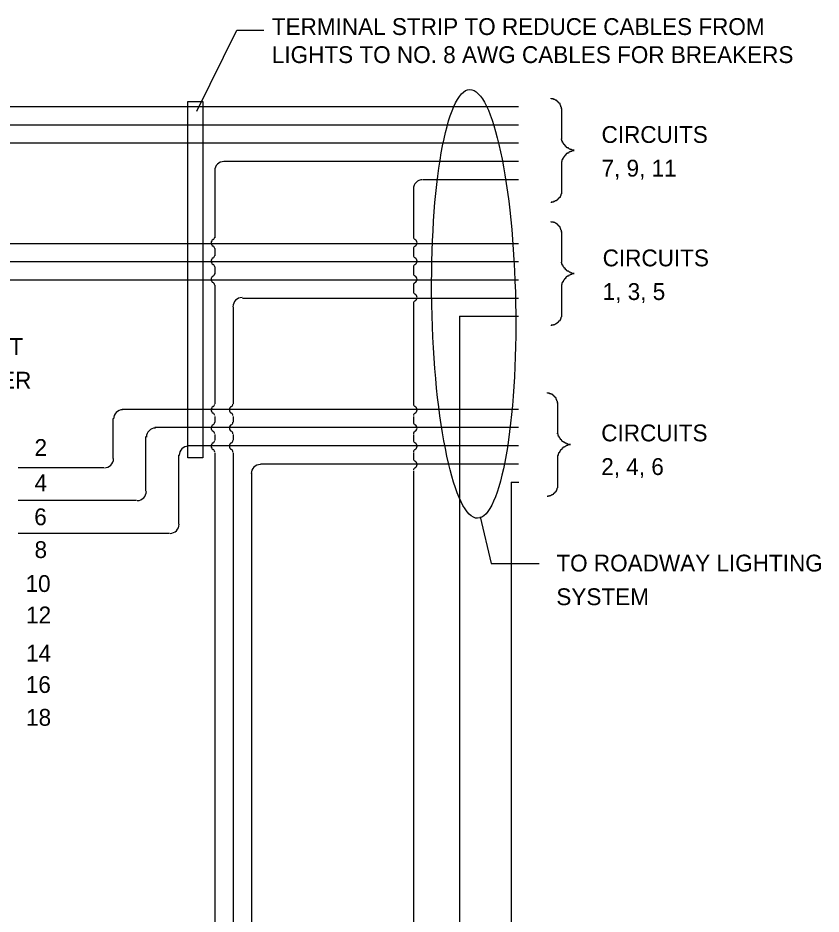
# Model space of a CAD drawing. Extents: x 10006.6 to 10036.5, y 10000 to 10010.3.
# Drawn here: x 10033.106 to 10035.968, y 10007.122 to 10010.317 of the extents above; entities that cross this region are included whole.
import ezdxf

# ---------------------------------------------------------------- set-up
doc = ezdxf.new("R2010")
doc.units = 0
for name, color, linetype in [('Default', 7, 'Continuous'), ('DETL-LINE', 7, 'Continuous'), ('DETL-NOTE', 7, 'Continuous'), ('TTLB-TEXT', 7, 'Continuous')]:
    doc.layers.add(name, color=color, linetype=linetype)

msp = doc.modelspace()

# ---------------------------------------------------------------- linework, layer by layer
at = {"layer": 'Default'}
msp.add_lwpolyline([(10033.7652, 10008.7486), (10033.7118, 10008.7486), (10033.7118, 10010.0192), (10033.7652, 10010.0192)], close=True, dxfattribs=at)
at = {"layer": 'DETL-LINE'}
for p, q in [((10031.28, 10010.001), (10034.89, 10010.001)), ((10031.378, 10009.936), (10034.89, 10009.936)), ((10031.475, 10009.871), (10034.89, 10009.871)), ((10033.841, 10009.806), (10034.89, 10009.806)), ((10033.809, 10009.533), (10033.809, 10009.773)), ((10034.55, 10009.741), (10034.89, 10009.741)), ((10034.517, 10009.533), (10034.517, 10009.708)), ((10031.677, 10009.513), (10034.89, 10009.513)), ((10033.809, 10009.468), (10033.809, 10009.494)), ((10034.517, 10009.468), (10034.517, 10009.494)), ((10031.774, 10009.448), (10034.89, 10009.448)), ((10033.809, 10009.403), (10033.809, 10009.429)), ((10034.517, 10009.403), (10034.517, 10009.429)), ((10031.891, 10009.383), (10034.89, 10009.383)), ((10033.809, 10008.941), (10033.809, 10009.364)), ((10034.517, 10009.338), (10034.517, 10009.364)), ((10033.906, 10009.318), (10034.89, 10009.318)), ((10033.874, 10008.941), (10033.874, 10009.286)), ((10034.517, 10008.941), (10034.517, 10009.299)), ((10034.6795, 10009.253), (10034.89, 10009.253)), ((10033.477, 10008.922), (10034.89, 10008.922)), ((10033.809, 10008.876), (10033.809, 10008.896)), ((10033.874, 10008.876), (10033.874, 10008.896)), ((10034.517, 10008.876), (10034.517, 10008.896)), ((10033.445, 10008.746), (10033.445, 10008.889)), ((10033.594, 10008.857), (10034.89, 10008.857)), ((10033.562, 10008.629), (10033.562, 10008.824)), ((10033.809, 10008.811), (10033.809, 10008.831)), ((10033.874, 10008.811), (10033.874, 10008.831)), ((10034.517, 10008.811), (10034.517, 10008.831)), ((10033.711, 10008.792), (10034.89, 10008.792)), ((10033.679, 10008.512), (10033.679, 10008.759)), ((10033.809, 10006.452), (10033.809, 10008.766)), ((10033.874, 10006.341), (10033.874, 10008.766)), ((10034.517, 10008.746), (10034.517, 10008.766)), ((10033.107, 10008.714), (10033.412, 10008.714)), ((10033.971, 10008.727), (10034.89, 10008.727)), ((10033.939, 10006.237), (10033.939, 10008.694)), ((10034.517, 10005.9973), (10034.517, 10008.701)), ((10034.864, 10008.662), (10034.8915, 10008.662)), ((10033.107, 10008.597), (10033.529, 10008.597)), ((10033.107, 10008.48), (10033.646, 10008.48))]:
    msp.add_line(p, q, dxfattribs=at)
for centre, radius, start, end in [((10033.8399, 10009.7723), 0.0325, 90, 180), ((10034.548, 10009.7073), 0.0325, 90, 180), ((10033.7976, 10009.5351), 0.00975, 295.3769, 0), ((10034.5253, 10009.5351), 0.00975, 180, 244.6231), ((10033.8074, 10009.5146), 0.013, 115.3769, 244.6231), ((10034.5155, 10009.5146), 0.013, 295.3769, 64.6231), ((10033.7976, 10009.494), 0.00975, 0, 64.6231), ((10034.5253, 10009.494), 0.00975, 115.3769, 180), ((10033.8074, 10009.4496), 0.013, 115.3769, 244.6231), ((10033.7976, 10009.4701), 0.00975, 295.3769, 0), ((10034.5253, 10009.4701), 0.00975, 180, 244.6231), ((10034.5155, 10009.4496), 0.013, 295.3769, 64.6231), ((10033.7976, 10009.429), 0.00975, 0, 64.6231), ((10034.5253, 10009.429), 0.00975, 115.3769, 180), ((10033.8074, 10009.3846), 0.013, 115.3769, 244.6231), ((10033.7976, 10009.4051), 0.00975, 295.3769, 0), ((10034.5253, 10009.4051), 0.00975, 180, 244.6231), ((10034.5155, 10009.3846), 0.013, 295.3769, 64.6231), ((10033.7976, 10009.364), 0.00975, 0, 64.6231), ((10034.5253, 10009.364), 0.00975, 115.3769, 180), ((10033.9049, 10009.2871), 0.0325, 90, 180), ((10034.5253, 10009.3401), 0.00975, 180, 244.6231), ((10034.5155, 10009.3196), 0.013, 295.3769, 64.6231), ((10034.5253, 10009.299), 0.00975, 115.3769, 180), ((10033.8074, 10008.9195), 0.013, 115.3769, 244.6231), ((10033.7976, 10008.9401), 0.00975, 295.3769, 0), ((10033.8724, 10008.9195), 0.013, 115.3769, 244.6231), ((10033.8626, 10008.9401), 0.00975, 295.3769, 0), ((10034.5253, 10008.9401), 0.00975, 180, 244.6231), ((10034.5155, 10008.9195), 0.013, 295.3769, 64.6231), ((10033.4791, 10008.887), 0.0325, 90, 180), ((10033.7976, 10008.899), 0.00975, 0, 64.6231), ((10033.8626, 10008.899), 0.00975, 0, 64.6231), ((10034.5253, 10008.899), 0.00975, 115.3769, 180), ((10033.8074, 10008.8545), 0.013, 115.3769, 244.6231), ((10033.7976, 10008.8751), 0.00975, 295.3769, 0), ((10033.8724, 10008.8545), 0.013, 115.3769, 244.6231), ((10033.8626, 10008.8751), 0.00975, 295.3769, 0), ((10034.5253, 10008.8751), 0.00975, 180, 244.6231), ((10034.5155, 10008.8545), 0.013, 295.3769, 64.6231), ((10033.5961, 10008.822), 0.0325, 90, 180), ((10033.7976, 10008.834), 0.00975, 0, 64.6231), ((10033.8626, 10008.834), 0.00975, 0, 64.6231), ((10034.5253, 10008.834), 0.00975, 115.3769, 180), ((10033.8074, 10008.7895), 0.013, 115.3769, 244.6231), ((10033.7976, 10008.8101), 0.00975, 295.3769, 0), ((10033.8724, 10008.7895), 0.013, 115.3769, 244.6231), ((10033.8626, 10008.8101), 0.00975, 295.3769, 0), ((10034.5253, 10008.8101), 0.00975, 180, 244.6231), ((10034.5155, 10008.7895), 0.013, 295.3769, 64.6231), ((10033.7131, 10008.757), 0.0325, 90, 180), ((10033.7976, 10008.769), 0.00975, 0, 64.6231), ((10033.8626, 10008.769), 0.00975, 0, 64.6231), ((10034.5253, 10008.769), 0.00975, 115.3769, 180), ((10033.4141, 10008.7455), 0.0325, 270, 0), ((10034.5253, 10008.7451), 0.00975, 180, 244.6231), ((10034.5155, 10008.7245), 0.013, 295.3769, 64.6231), ((10033.9699, 10008.692), 0.0325, 90, 180), ((10034.5253, 10008.704), 0.00975, 115.3769, 180), ((10033.5311, 10008.6285), 0.0325, 270, 0), ((10033.6481, 10008.5115), 0.0325, 270, 0)]:
    msp.add_arc(centre, radius, start, end, dxfattribs=at)
at = {"layer": 'DETL-NOTE'}
for p, q in [((10034.794, 10008.371), (10034.755, 10008.538)), ((10034.793, 10008.371), (10034.964, 10008.371))]:
    msp.add_line(p, q, dxfattribs=at)
for points in [[(10033.7438, 10009.9846), (10033.8862, 10010.2729), (10033.9824, 10010.2729)], [(10035.043, 10009.992), (10035.043, 10009.994), (10035.043, 10009.996), (10035.043, 10009.998), (10035.041, 10010), (10035.041, 10010.002), (10035.041, 10010.004), (10035.04, 10010.004), (10035.04, 10010.006), (10035.04, 10010.007), (10035.038, 10010.007), (10035.038, 10010.009), (10035.038, 10010.011), (10035.036, 10010.011), (10035.036, 10010.013), (10035.034, 10010.013), (10035.034, 10010.015), (10035.032, 10010.015), (10035.032, 10010.017), (10035.03, 10010.017), (10035.03, 10010.019), (10035.028, 10010.019), (10035.028, 10010.021), (10035.026, 10010.021), (10035.026, 10010.023), (10035.024, 10010.023), (10035.023, 10010.023), (10035.023, 10010.024), (10035.021, 10010.024), (10035.019, 10010.026), (10035.017, 10010.026), (10035.015, 10010.026), (10035.015, 10010.028), (10035.013, 10010.028), (10035.011, 10010.028), (10035.009, 10010.028), (10035.007, 10010.028), (10035.007, 10010.03)], [(10035.043, 10009.994), (10035.043, 10009.885)], [(10035.089, 10009.845), (10035.087, 10009.845), (10035.085, 10009.845), (10035.083, 10009.845), (10035.081, 10009.845), (10035.079, 10009.847), (10035.077, 10009.847), (10035.075, 10009.847), (10035.074, 10009.849), (10035.072, 10009.849), (10035.07, 10009.851), (10035.068, 10009.851), (10035.068, 10009.853), (10035.066, 10009.853), (10035.064, 10009.853), (10035.064, 10009.854), (10035.062, 10009.854), (10035.062, 10009.856), (10035.06, 10009.856), (10035.06, 10009.858), (10035.058, 10009.858), (10035.058, 10009.86), (10035.057, 10009.86), (10035.057, 10009.862), (10035.055, 10009.862), (10035.055, 10009.864), (10035.053, 10009.864), (10035.053, 10009.866), (10035.051, 10009.868), (10035.051, 10009.87), (10035.049, 10009.87), (10035.049, 10009.871), (10035.049, 10009.873), (10035.047, 10009.873), (10035.047, 10009.875), (10035.047, 10009.877), (10035.045, 10009.877), (10035.045, 10009.879), (10035.045, 10009.881), (10035.045, 10009.883), (10035.043, 10009.883), (10035.043, 10009.885)], [(10035.089, 10009.843), (10035.087, 10009.843), (10035.085, 10009.843), (10035.083, 10009.843), (10035.081, 10009.843), (10035.079, 10009.841), (10035.077, 10009.841), (10035.075, 10009.841), (10035.074, 10009.839), (10035.072, 10009.839), (10035.07, 10009.837), (10035.068, 10009.837), (10035.068, 10009.835), (10035.066, 10009.835), (10035.064, 10009.835), (10035.064, 10009.834), (10035.062, 10009.834), (10035.062, 10009.832), (10035.06, 10009.832), (10035.06, 10009.83), (10035.058, 10009.83), (10035.058, 10009.828), (10035.057, 10009.828), (10035.057, 10009.826), (10035.055, 10009.826), (10035.055, 10009.824), (10035.053, 10009.824), (10035.053, 10009.822), (10035.051, 10009.82), (10035.051, 10009.818), (10035.049, 10009.818), (10035.049, 10009.817), (10035.049, 10009.815), (10035.047, 10009.815), (10035.047, 10009.813), (10035.047, 10009.811), (10035.045, 10009.811), (10035.045, 10009.809), (10035.045, 10009.807), (10035.045, 10009.805), (10035.043, 10009.805), (10035.043, 10009.803)], [(10035.043, 10009.803), (10035.043, 10009.694)], [(10035.043, 10009.696), (10035.043, 10009.694), (10035.043, 10009.692), (10035.043, 10009.69), (10035.041, 10009.688), (10035.041, 10009.686), (10035.041, 10009.684), (10035.04, 10009.684), (10035.04, 10009.682), (10035.04, 10009.681), (10035.038, 10009.681), (10035.038, 10009.679), (10035.038, 10009.677), (10035.036, 10009.677), (10035.036, 10009.675), (10035.034, 10009.675), (10035.034, 10009.673), (10035.032, 10009.673), (10035.032, 10009.671), (10035.03, 10009.671), (10035.03, 10009.669), (10035.028, 10009.669), (10035.028, 10009.667), (10035.026, 10009.667), (10035.026, 10009.665), (10035.024, 10009.665), (10035.023, 10009.665), (10035.023, 10009.664), (10035.021, 10009.664), (10035.019, 10009.662), (10035.017, 10009.662), (10035.015, 10009.662), (10035.015, 10009.66), (10035.013, 10009.66), (10035.011, 10009.66), (10035.009, 10009.66), (10035.007, 10009.66), (10035.007, 10009.658)], [(10035.043, 10009.553), (10035.043, 10009.555), (10035.043, 10009.557), (10035.043, 10009.559), (10035.041, 10009.561), (10035.041, 10009.563), (10035.041, 10009.565), (10035.04, 10009.565), (10035.04, 10009.567), (10035.04, 10009.568), (10035.038, 10009.568), (10035.038, 10009.57), (10035.038, 10009.572), (10035.036, 10009.572), (10035.036, 10009.574), (10035.034, 10009.574), (10035.034, 10009.576), (10035.032, 10009.576), (10035.032, 10009.578), (10035.03, 10009.578), (10035.03, 10009.58), (10035.028, 10009.58), (10035.028, 10009.582), (10035.026, 10009.582), (10035.026, 10009.584), (10035.024, 10009.584), (10035.023, 10009.584), (10035.023, 10009.585), (10035.021, 10009.585), (10035.019, 10009.587), (10035.017, 10009.587), (10035.015, 10009.587), (10035.015, 10009.589), (10035.013, 10009.589), (10035.011, 10009.589), (10035.009, 10009.589), (10035.007, 10009.589), (10035.007, 10009.591)], [(10035.043, 10009.555), (10035.043, 10009.446)], [(10035.089, 10009.406), (10035.087, 10009.406), (10035.085, 10009.406), (10035.083, 10009.406), (10035.081, 10009.406), (10035.079, 10009.408), (10035.077, 10009.408), (10035.075, 10009.408), (10035.074, 10009.41), (10035.072, 10009.41), (10035.07, 10009.412), (10035.068, 10009.412), (10035.068, 10009.414), (10035.066, 10009.414), (10035.064, 10009.414), (10035.064, 10009.415), (10035.062, 10009.415), (10035.062, 10009.417), (10035.06, 10009.417), (10035.06, 10009.419), (10035.058, 10009.419), (10035.058, 10009.421), (10035.057, 10009.421), (10035.057, 10009.423), (10035.055, 10009.423), (10035.055, 10009.425), (10035.053, 10009.425), (10035.053, 10009.427), (10035.051, 10009.429), (10035.051, 10009.431), (10035.049, 10009.431), (10035.049, 10009.432), (10035.049, 10009.434), (10035.047, 10009.434), (10035.047, 10009.436), (10035.047, 10009.438), (10035.045, 10009.438), (10035.045, 10009.44), (10035.045, 10009.442), (10035.045, 10009.444), (10035.043, 10009.444), (10035.043, 10009.446)], [(10035.089, 10009.404), (10035.087, 10009.404), (10035.085, 10009.404), (10035.083, 10009.404), (10035.081, 10009.404), (10035.079, 10009.402), (10035.077, 10009.402), (10035.075, 10009.402), (10035.074, 10009.4), (10035.072, 10009.4), (10035.07, 10009.398), (10035.068, 10009.398), (10035.068, 10009.396), (10035.066, 10009.396), (10035.064, 10009.396), (10035.064, 10009.395), (10035.062, 10009.395), (10035.062, 10009.393), (10035.06, 10009.393), (10035.06, 10009.391), (10035.058, 10009.391), (10035.058, 10009.389), (10035.057, 10009.389), (10035.057, 10009.387), (10035.055, 10009.387), (10035.055, 10009.385), (10035.053, 10009.385), (10035.053, 10009.383), (10035.051, 10009.381), (10035.051, 10009.379), (10035.049, 10009.379), (10035.049, 10009.378), (10035.049, 10009.376), (10035.047, 10009.376), (10035.047, 10009.374), (10035.047, 10009.372), (10035.045, 10009.372), (10035.045, 10009.37), (10035.045, 10009.368), (10035.045, 10009.366), (10035.043, 10009.366), (10035.043, 10009.364)], [(10035.043, 10009.364), (10035.043, 10009.255)], [(10035.043, 10009.257), (10035.043, 10009.255), (10035.043, 10009.253), (10035.043, 10009.251), (10035.041, 10009.249), (10035.041, 10009.247), (10035.041, 10009.245), (10035.04, 10009.245), (10035.04, 10009.243), (10035.04, 10009.242), (10035.038, 10009.242), (10035.038, 10009.24), (10035.038, 10009.238), (10035.036, 10009.238), (10035.036, 10009.236), (10035.034, 10009.236), (10035.034, 10009.234), (10035.032, 10009.234), (10035.032, 10009.232), (10035.03, 10009.232), (10035.03, 10009.23), (10035.028, 10009.23), (10035.028, 10009.228), (10035.026, 10009.228), (10035.026, 10009.226), (10035.024, 10009.226), (10035.023, 10009.226), (10035.023, 10009.225), (10035.021, 10009.225), (10035.019, 10009.223), (10035.017, 10009.223), (10035.015, 10009.223), (10035.015, 10009.221), (10035.013, 10009.221), (10035.011, 10009.221), (10035.009, 10009.221), (10035.007, 10009.221), (10035.007, 10009.219)], [(10035.029, 10008.943), (10035.029, 10008.945), (10035.029, 10008.947), (10035.029, 10008.949), (10035.027, 10008.951), (10035.027, 10008.953), (10035.027, 10008.955), (10035.026, 10008.955), (10035.026, 10008.957), (10035.026, 10008.958), (10035.024, 10008.958), (10035.024, 10008.96), (10035.024, 10008.962), (10035.022, 10008.962), (10035.022, 10008.964), (10035.02, 10008.964), (10035.02, 10008.966), (10035.018, 10008.966), (10035.018, 10008.968), (10035.016, 10008.968), (10035.016, 10008.97), (10035.014, 10008.97), (10035.014, 10008.972), (10035.012, 10008.972), (10035.012, 10008.974), (10035.01, 10008.974), (10035.009, 10008.974), (10035.009, 10008.975), (10035.007, 10008.975), (10035.005, 10008.977), (10035.003, 10008.977), (10035.001, 10008.977), (10035.001, 10008.979), (10034.999, 10008.979), (10034.997, 10008.979), (10034.995, 10008.979), (10034.993, 10008.979), (10034.993, 10008.981)], [(10035.029, 10008.945), (10035.029, 10008.836)], [(10035.075, 10008.796), (10035.073, 10008.796), (10035.071, 10008.796), (10035.069, 10008.796), (10035.067, 10008.796), (10035.065, 10008.798), (10035.063, 10008.798), (10035.061, 10008.798), (10035.06, 10008.8), (10035.058, 10008.8), (10035.056, 10008.802), (10035.054, 10008.802), (10035.054, 10008.804), (10035.052, 10008.804), (10035.05, 10008.804), (10035.05, 10008.805), (10035.048, 10008.805), (10035.048, 10008.807), (10035.046, 10008.807), (10035.046, 10008.809), (10035.044, 10008.809), (10035.044, 10008.811), (10035.043, 10008.811), (10035.043, 10008.813), (10035.041, 10008.813), (10035.041, 10008.815), (10035.039, 10008.815), (10035.039, 10008.817), (10035.037, 10008.819), (10035.037, 10008.821), (10035.035, 10008.821), (10035.035, 10008.822), (10035.035, 10008.824), (10035.033, 10008.824), (10035.033, 10008.826), (10035.033, 10008.828), (10035.031, 10008.828), (10035.031, 10008.83), (10035.031, 10008.832), (10035.031, 10008.834), (10035.029, 10008.834), (10035.029, 10008.836)], [(10035.075, 10008.794), (10035.073, 10008.794), (10035.071, 10008.794), (10035.069, 10008.794), (10035.067, 10008.794), (10035.065, 10008.792), (10035.063, 10008.792), (10035.061, 10008.792), (10035.06, 10008.79), (10035.058, 10008.79), (10035.056, 10008.788), (10035.054, 10008.788), (10035.054, 10008.786), (10035.052, 10008.786), (10035.05, 10008.786), (10035.05, 10008.785), (10035.048, 10008.785), (10035.048, 10008.783), (10035.046, 10008.783), (10035.046, 10008.781), (10035.044, 10008.781), (10035.044, 10008.779), (10035.043, 10008.779), (10035.043, 10008.777), (10035.041, 10008.777), (10035.041, 10008.775), (10035.039, 10008.775), (10035.039, 10008.773), (10035.037, 10008.771), (10035.037, 10008.769), (10035.035, 10008.769), (10035.035, 10008.768), (10035.035, 10008.766), (10035.033, 10008.766), (10035.033, 10008.764), (10035.033, 10008.762), (10035.031, 10008.762), (10035.031, 10008.76), (10035.031, 10008.758), (10035.031, 10008.756), (10035.029, 10008.756), (10035.029, 10008.754)], [(10035.029, 10008.754), (10035.029, 10008.645)], [(10035.029, 10008.647), (10035.029, 10008.645), (10035.029, 10008.643), (10035.029, 10008.641), (10035.027, 10008.639), (10035.027, 10008.637), (10035.027, 10008.635), (10035.026, 10008.635), (10035.026, 10008.633), (10035.026, 10008.632), (10035.024, 10008.632), (10035.024, 10008.63), (10035.024, 10008.628), (10035.022, 10008.628), (10035.022, 10008.626), (10035.02, 10008.626), (10035.02, 10008.624), (10035.018, 10008.624), (10035.018, 10008.622), (10035.016, 10008.622), (10035.016, 10008.62), (10035.014, 10008.62), (10035.014, 10008.618), (10035.012, 10008.618), (10035.012, 10008.616), (10035.01, 10008.616), (10035.009, 10008.616), (10035.009, 10008.615), (10035.007, 10008.615), (10035.005, 10008.613), (10035.003, 10008.613), (10035.001, 10008.613), (10035.001, 10008.611), (10034.999, 10008.611), (10034.997, 10008.611), (10034.995, 10008.611), (10034.993, 10008.611), (10034.993, 10008.609)]]:
    msp.add_lwpolyline(points, dxfattribs=at)
msp.add_ellipse((10034.7304, 10009.2971), major_axis=(0.014, -0.7645), ratio=0.195358, dxfattribs=at)
msp.add_ellipse((10034.7304, 10009.2971), major_axis=(0.014, -0.7645), ratio=0.195358, dxfattribs=at)
at = {"layer": 'TTLB-TEXT'}
for p, q in [((10034.6795, 10009.253), (10034.6795, 10005.8506)), ((10034.864, 10008.662), (10034.864, 10005.7436))]:
    msp.add_line(p, q, dxfattribs=at)

# ---------------------------------------------------------------- texts
at = {"layer": 'DETL-NOTE'}
for s, p in [('TERMINAL STRIP TO REDUCE CABLES FROM', (10034.0108, 10010.2558)), ('LIGHTS TO NO. 8 AWG CABLES FOR BREAKERS', (10034.0108, 10010.1558)), ('CIRCUITS', (10035.186, 10009.871)), ('7, 9, 11', (10035.186, 10009.751)), ('CIRCUITS', (10035.19, 10009.431)), ('1, 3, 5', (10035.19, 10009.311)), ('BREAKERS. SEE CONTRACT', (10032.015, 10009.115)), ('DOCUMENTS FOR NUMBER', (10032.075, 10008.995)), ('CIRCUITS', (10035.185, 10008.807)), ('2', (10033.165, 10008.755)), ('2, 4, 6', (10035.185, 10008.687)), ('4', (10033.165, 10008.629)), ('6', (10033.164, 10008.508)), ('8', (10033.165, 10008.391)), ('TO ROADWAY LIGHTING', (10035.025, 10008.343)), ('10', (10033.133, 10008.27)), ('SYSTEM', (10035.025, 10008.223)), ('12', (10033.135, 10008.158)), ('14', (10033.135, 10008.022)), ('16', (10033.134, 10007.91)), ('18', (10033.135, 10007.793))]:
    msp.add_text(s, height=0.06, dxfattribs=at).set_placement(p)

doc.saveas('drawing.dxf')
